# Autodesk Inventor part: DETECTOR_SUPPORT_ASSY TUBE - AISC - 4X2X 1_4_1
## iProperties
Shininess: 64.0
Length Units: 11272
Angle Units: 11279
Time Units: 11290
Mass Units: 11286
Length Display Precision: 3
Angle Display Precision: 2
Compacted: True
Part Number: DETECTOR_SUPPORT_ASSY TUBE - AISC - 4X2X 1_4_1
Document SubType Name: Modeling
Created: 2004-08
Designer: John Blackburn
Material: MILD_STEEL
Manufacturer: Standard
Standards Organization: Custom
Density: 0.0
Volumn: 0.0
Area: 0.0
PropertySet Name: Model Information
Control State: 0
Master: False
Checked Out: False
Author: John Blackburn
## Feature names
1. BaseExt [Extrusion]
2. Fillet1
3. Fillet2
